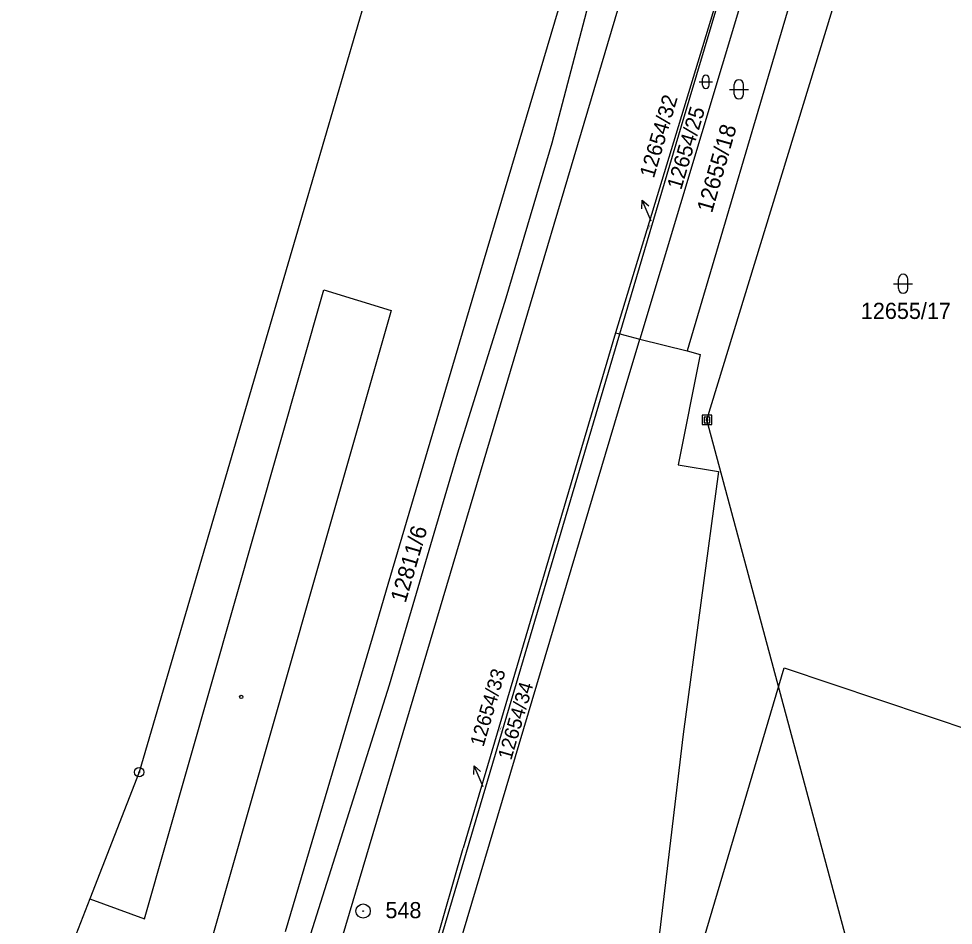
# Model space of a CAD drawing. Extents: x -822293 to -820259, y -1071573 to -1068794.
# Drawn here: x -820534.7 to -820436.3, y -1069255.1 to -1069159.7 of the extents above; entities that cross this region are included whole.
import ezdxf

# ---------------------------------------------------------------- set-up
doc = ezdxf.new("R2010")
doc.units = 0
for name, color, linetype in [('Vrstva 1', 7, 'Continuous'), ('Vrstva 12', 7, 'Continuous'), ('Vrstva 16', 7, 'Continuous'), ('Vrstva 17', 7, 'Continuous'), ('Vrstva 18', 7, 'Continuous'), ('Vrstva 24', 7, 'Continuous'), ('Vrstva 25', 7, 'Continuous'), ('Vrstva 26', 7, 'Continuous'), ('Vrstva 4', 7, 'Continuous')]:
    doc.layers.add(name, color=color, linetype=linetype)

msp = doc.modelspace()

# ---------------------------------------------------------------- linework, layer by layer
at = {"layer": 'Vrstva 1'}
for p, q in [((-820466.09, -1069048.01), (-820504.69, -1069179.81)), ((-820456.39, -1069141.82), (-820471.89, -1069192.79)), ((-820453.97, -1069142.37), (-820469.32, -1069193.43)), ((-820449.36, -1069143.92), (-820464.35, -1069194.67)), ((-820508.96, -1069284.39), (-820468.47, -1069148.07)), ((-820475.28, -1069149.84), (-820485.8, -1069185.35)), ((-820464.94, -1069171), (-820459.86, -1069154.03)), ((-820474.58, -1069157.57), (-820478.57, -1069172.82)), ((-820471.43, -1069192.9), (-820464.94, -1069171)), ((-820478.57, -1069172.82), (-820483.43, -1069189.12)), ((-820504.69, -1069179.81), (-820522.03, -1069239.01)), ((-820485.8, -1069185.35), (-820495.84, -1069219.27)), ((-820483.43, -1069189.12), (-820488.52, -1069205.45)), ((-820471.89, -1069192.79), (-820487.91, -1069247)), ((-820471.89, -1069192.79), (-820471.43, -1069192.9)), ((-820508.17, -1069316.98), (-820471.43, -1069192.9)), ((-820471.43, -1069192.9), (-820469.32, -1069193.43)), ((-820471.09, -1069199.3), (-820469.32, -1069193.43)), ((-820469.32, -1069193.43), (-820464.35, -1069194.67)), ((-820464.35, -1069194.67), (-820462.95, -1069195.07)), ((-820462.95, -1069195.07), (-820465.28, -1069206.66)), ((-820494.15, -1069276.86), (-820471.09, -1069199.3)), ((-820488.52, -1069205.45), (-820495.7, -1069229.85)), ((-820465.28, -1069206.66), (-820461.04, -1069207.36)), ((-820461.04, -1069207.36), (-820464.74, -1069235.02)), ((-820495.84, -1069219.27), (-820497.51, -1069224.9)), ((-820497.51, -1069224.9), (-820506.66, -1069255.8)), ((-820471.19, -1069285.48), (-820454.11, -1069228.02)), ((-820454.11, -1069228.02), (-820426.24, -1069237.41)), ((-820495.7, -1069229.85), (-820508.01, -1069268.82)), ((-820464.74, -1069235.02), (-820469.34, -1069273.4)), ((-820522.03, -1069239.01), (-820527.23, -1069252.34)), ((-820508.17, -1069316.98), (-820487.91, -1069247)), ((-820527.23, -1069252.34), (-820534.71, -1069271.52))]:
    msp.add_line(p, q, dxfattribs=at)
at = {"layer": 'Vrstva 12'}
for p, q in [((-820462.25, -1069201.94), (-820438.93, -1069125.74)), ((-820428.56, -1069327.25), (-820462.25, -1069201.94))]:
    msp.add_line(p, q, dxfattribs=at)
at = {"layer": 'Vrstva 16'}
for p, q in [((-820468.12, -1069181.04), (-820469.073, -1069178.837)), ((-820485.81, -1069240.56), (-820486.762, -1069238.357))]:
    msp.add_line(p, q, dxfattribs=at)
for points in [[(-820469.123, -1069179.73), (-820469.073, -1069178.837), (-820468.388, -1069179.413)], [(-820486.812, -1069239.25), (-820486.762, -1069238.357), (-820486.078, -1069238.933)]]:
    msp.add_lwpolyline(points, dxfattribs=at)
at = {"layer": 'Vrstva 24'}
for centre, radius in [((-820522.03, -1069239.01), 0.5), ((-820522.03, -1069239.01), 0.0327), ((-820498.45, -1069253.63), 0.75), ((-820498.45, -1069253.63), 0.0327)]:
    msp.add_circle(centre, radius, dxfattribs=at)
at = {"layer": 'Vrstva 25'}
for p, q in [((-820462.73, -1069166.71), (-820462.73, -1069166.01)), ((-820462.03, -1069166.71), (-820462.03, -1069166.01)), ((-820463.08, -1069166.36), (-820461.68, -1069166.36)), ((-820459.89, -1069167.16), (-820457.89, -1069167.16)), ((-820459.39, -1069167.66), (-820459.39, -1069166.66)), ((-820458.39, -1069167.66), (-820458.39, -1069166.66)), ((-820442.6, -1069187.62), (-820440.6, -1069187.62)), ((-820442.1, -1069188.12), (-820442.1, -1069187.12)), ((-820441.1, -1069188.12), (-820441.1, -1069187.12))]:
    msp.add_line(p, q, dxfattribs=at)
msp.add_circle((-820511.28, -1069231.1), 0.175, dxfattribs=at)
for centre, radius, start, end in [((-820462.38, -1069166.01), 0.35, 0, 180), ((-820458.89, -1069166.66), 0.5, 0, 180), ((-820462.38, -1069166.71), 0.35, 180, 0), ((-820458.89, -1069167.66), 0.5, 180, 0), ((-820441.6, -1069187.12), 0.5, 0, 180), ((-820441.6, -1069188.12), 0.5, 180, 0)]:
    msp.add_arc(centre, radius, start, end, dxfattribs=at)
at = {"layer": 'Vrstva 26'}
for points in [[(-820461.75, -1069201.44), (-820462.75, -1069201.44), (-820462.75, -1069202.44), (-820461.75, -1069202.44)], [(-820461.95, -1069201.64), (-820462.55, -1069201.64), (-820462.55, -1069202.24), (-820461.95, -1069202.24)], [(-820462.35, -1069202.04), (-820462.15, -1069202.04), (-820462.15, -1069201.84), (-820462.35, -1069201.84)]]:
    msp.add_lwpolyline(points, close=True, dxfattribs=at)
at = {"layer": 'Vrstva 4'}
for p, q in [((-820521.48, -1069254.45), (-820502.58, -1069188.26)), ((-820502.58, -1069188.26), (-820495.5, -1069190.43)), ((-820495.5, -1069190.43), (-820520.01, -1069276.16)), ((-820527.23, -1069252.34), (-820521.48, -1069254.45))]:
    msp.add_line(p, q, dxfattribs=at)

# ---------------------------------------------------------------- texts
at = {"layer": 'Vrstva 16'}
for s, height, rotation, p in [('12654/32', 1.6, 73.51047, (-820467.847, -1069176.585)), ('12654/33', 1.5, 73.62504, (-820485.788, -1069236.426))]:
    msp.add_text(s, height=height, rotation=rotation, dxfattribs=at).set_placement(p)
at = {"layer": 'Vrstva 17'}
msp.add_text('548', height=1.7, dxfattribs=at).set_placement((-820496.102, -1069254.38))
at = {"layer": 'Vrstva 18'}
for s, height, rotation, p in [('12654/25', 1.6, 73.5678, (-820464.966, -1069177.82)), ('12655/18', 1.7, 74.02617, (-820461.722, -1069180.248)), ('12654/32', 0.1, 73.51047, (-820468.345, -1069181.959)), ('12811/6', 1.7, 73.62504, (-820493.981, -1069221.271)), ('12654/34', 1.5, 73.62504, (-820482.863, -1069237.824)), ('12654/33', 0.1, 73.62504, (-820484.025, -1069234.78))]:
    msp.add_text(s, height=height, rotation=rotation, dxfattribs=at).set_placement(p)
msp.add_text('12655/17', height=1.7, dxfattribs=at).set_placement((-820446.052, -1069191.32))

doc.saveas('drawing.dxf')
